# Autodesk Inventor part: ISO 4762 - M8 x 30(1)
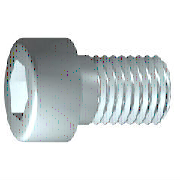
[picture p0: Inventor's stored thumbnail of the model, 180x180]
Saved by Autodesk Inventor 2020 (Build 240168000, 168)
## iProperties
Created: 2019-01
Part Number: ISO 4762 - M8 x 30(1)
Material: Nerezová ocel 440C
Description: Šroub s válcovou hlavou s vnitřním šestihranem
Document SubType Name: Modeling
Standard: ISO 4762
Designer: doma
Standard Revision: Fourth edition 2004-03-01
Standards Organization: ISO
Language: cs-CZ
Size Designation: M8 x 30
Categories: <MemberInstance><Categories><Category DisplayName="Spojovací materiál" InternalName="e4da775c-781d-43d5-af7c-5136215cf5a6" Mnemonic="FSTN"><Category DisplayName
Density: 7.75 g/cm^3
Appearance: Pololeštěná
IsCustomPart: 0
Author: doma
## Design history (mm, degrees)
sketch "Náčrt1"
  geometry: L1 (-2, 0)-(30, 0); L2 (30, 0)-(30, 4); L3 (30, 4)-(3.125, 4); L4 (3.125, 4)-(2.358, 4); L5 (2.358, 4)-(0, 4); L6 (0, 4)-(0, 6.5); L7 (0, 6.5)-(-8, 6.5); L8 (-8, 6.5)-(-8, 3.464); L9 (-8, 3.464)-(-4, 3.464); L10 (-4, 3.464)-(-2, 0); L11 (-15.6, 0)-(37.6, 0) reference; L12 (0, -1.3)-(0, 7.8) reference; L13 (3.125, 4)-(0, 4)
  constraints: 22 end point, 6 parallel, 2 collinear, 2 perpendicular, 1 horizontal, 1 point on line
  dimensions: "d1" = 26.875 distance from line of L3.end L2 (= GEL); "d2" = 0.76691 distance of L4.end L3.end (computed from GAL); "d3" = 8 distance between parallel lines of L8 L6 (= KOH); "d4" = 4 distance of L8.end L9.end (= INTI); "d5" = 60 deg angle of L10 L1; "d6" = 8 diameter of L3 L1 (= GD); "d7" = 8 diameter of L5 L1 (= BDM); "d8" = 6.9282 diameter of L9 L1 (= 1.1547 x SW); "d9" = 13 diameter of L7 L1 (= KOD); "d26" = 30 distance between parallel lines of L12 L2 (= NLG)
revolve "Těleso" sketch "Náčrt1" stored, may be unused: angle "d10" = 90 deg
sketch "Náčrt2"
  geometry: L1 (0, -9.1)-(0, 9.1) reference; L2 (-9.1, 0)-(9.1, 0) reference; L3 (3.464, 0)-(1.732, -3); L4 (1.732, -3)-(-1.732, -3); L5 (-1.732, -3)-(-3.464, 0); L6 (-3.464, 0)-(-1.732, 3); L7 (-1.732, 3)-(1.732, 3); L8 (1.732, 3)-(3.464, 0); 2 further points
  constraints: 12 end point, 1 coincident, 1 horizontal alignment, 1 point on line, 12 other
extrude "Drážka" join sketch "Náčrt2" stored distance "d11" = 10; taper "d12" = 0 deg
workplane "Work Plane1"
fillet "Fillet2" dims "d30" = 0.1 (= R)
body "Solid1"
fillet "Zaoblení1" dims "d17" = 0.8 (= RR)
feature "Závit" dims "d13" = 26.875 (= GEL), "d14" = 0
chamfer "Zkosení1" distance "d15" = 0.76681 (= -0.5 x SPD + 0.5 x GD); stored, may be unused: second distance "d16" = 0.76681 (= GUL), angle "d27" = 45 deg
other parameters: "GD" = 8 [user parameter; used in 2 equation terms], "NLG" = 30 [user parameter; used in 1 equation term], "GEL" = 26.875 [user parameter; used in 2 equation terms], "KOD" = 13 [user parameter; used in 1 equation term], "KOH" = 8 [user parameter; used in 1 equation term], "INTI" = 4 [user parameter; used in 1 equation term], "GAL" = 0.76681 (= 0.61345 x PTC) [user parameter; used in 1 equation term], "GUL" = 0.76681 (= 0.61345 x PTC) [user parameter; used in 1 equation term], "BDM" = 8 (= NND) [user parameter; used in 1 equation term], "SW" = 6 [user parameter; used in 2 equation terms], "RR" = 0.8 [user parameter; used in 1 equation term], "SPD" = 6.46637 (= NND - 1.2269 x PTC) [user parameter; used in 1 equation term], "d19" = 0, "d28" = 0, "d29" = 0, "R" = 0.1 [user parameter; used in 1 equation term], "TOA" = 30 deg [user parameter], "GD1" = 6.46637 (= THREADDIA - 1.2269 x PTC) [user parameter], "THREADDIA" = 8 [user parameter; used in 1 equation term], "FAWI" = 45 deg [user parameter], "TPU" = 8 (computed from PTC) [user parameter], "PTC" = 1.25 [user parameter; used in 5 equation terms], "NND" = 8 [user parameter; used in 2 equation terms], "E0" = 6.93 (= 1.155 x SW) [user parameter]
